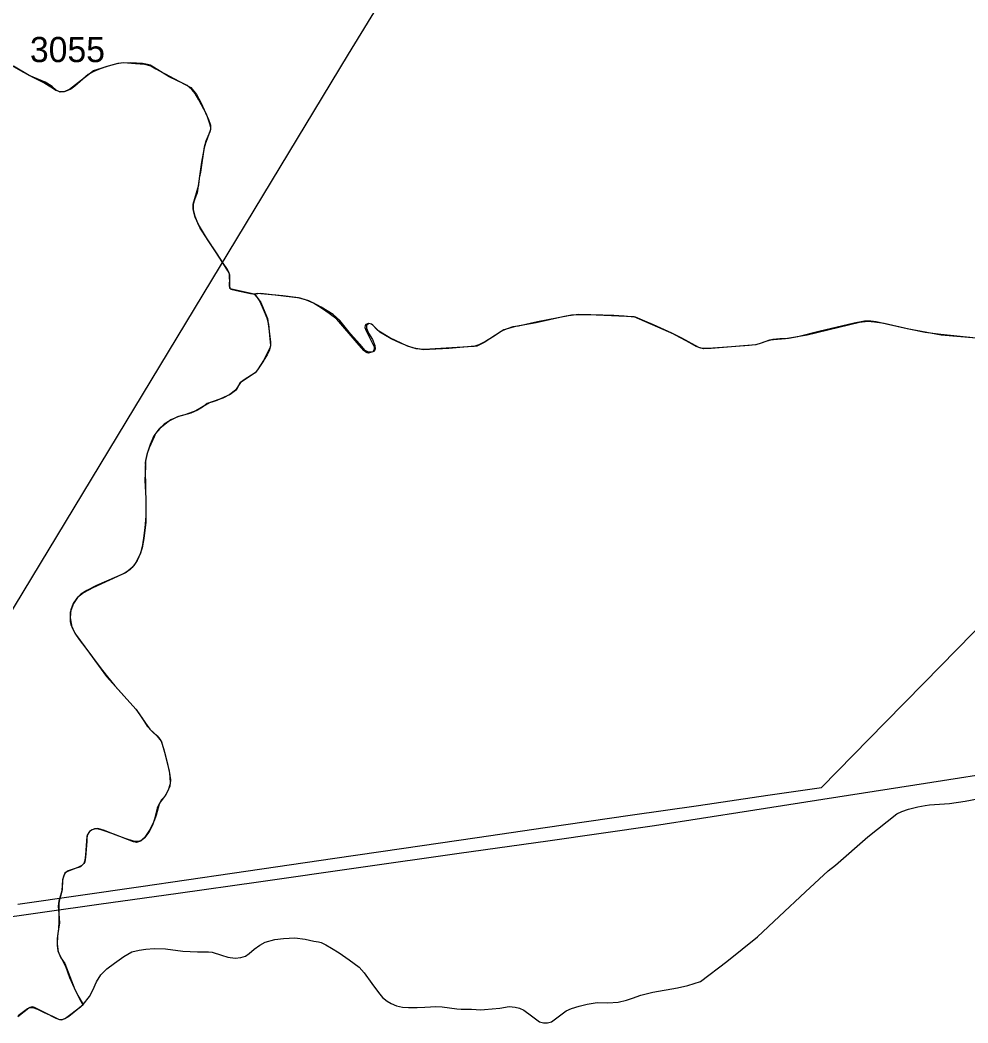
# Model space of a CAD drawing. Extents: x -789162 to -606354, y -1062736 to -945481.
# Drawn here: x -717217 to -713459, y -978569 to -974592 of the extents above; entities that cross this region are included whole.
import ezdxf

# ---------------------------------------------------------------- set-up
doc = ezdxf.new("R2010")
doc.units = 0
for name, color, linetype in [('_SIRSI VZTAHY_CYKLOTRASY MISTNI S', 7, 'Continuous'), ('_SIRSI VZTAHY_CYKLOTRASY MISTNI_POPIS', 7, 'Continuous'), ('_SIRSI VZTAHY_ELEKTRICKE VEDENI VN 220 kV S', 7, 'Continuous'), ('_SIRSI VZTAHY_ELEKTRICKE VEDENI VN 400 kV N', 7, 'Continuous'), ('_SIRSI VZTAHY_ELEKTRICKE VEDENI VN 400 kV S', 7, 'Continuous'), ('_SIRSI VZTAHY_OP vodnich zdroju II stupne', 7, 'Continuous'), ('_SIRSI VZTAHY_SILNICE III TRIDY_STAV', 7, 'Continuous')]:
    doc.layers.add(name, color=color, linetype=linetype)

msp = doc.modelspace()

# ---------------------------------------------------------------- linework, layer by layer
at = {"layer": '_SIRSI VZTAHY_CYKLOTRASY MISTNI S'}
for points in [[(-716288.8, -975678.1), (-716383.8, -975657.6), (-716385.9, -975643.3), (-716386.2, -975598.7), (-716392.7, -975586), (-716413.4, -975554.2), (-716442.2, -975509.8), (-716502.6, -975416.9), (-716522.6, -975373.6), (-716529.6, -975348.1), (-716530.9, -975340.5), (-716530.1, -975321.7), (-716508.3, -975245.2), (-716505.5, -975218.8), (-716500.4, -975194.4), (-716485.5, -975093.9), (-716478.5, -975070.9), (-716462.7, -975033.5), (-716461, -975024), (-716460.1, -975018.8), (-716463, -975006.8), (-716472.8, -974979.7), (-716478.3, -974964.6), (-716508.5, -974907.4), (-716523.3, -974882.7), (-716536.1, -974867), (-716555.1, -974851.5), (-716568, -974844), (-716626.3, -974816.2), (-716660.1, -974795.8), (-716688.3, -974777.9), (-716701.4, -974771.1), (-716712.1, -974767.6), (-716731.9, -974764.5), (-716755.7, -974762.6), (-716780.7, -974761.8), (-716815.5, -974761.9), (-716833, -974764.7), (-716873.1, -974776.3), (-716898.8, -974784.6), (-716924.1, -974795.5), (-716946.7, -974808), (-717000.1, -974854.4), (-717015.9, -974865.8), (-717031.4, -974872.6), (-717042.7, -974876.2), (-717057.8, -974877), (-717065.9, -974873.5), (-717073.3, -974869.4), (-717090.3, -974855.5), (-717111, -974841.5), (-717117.5, -974837.3), (-717180.4, -974810.9), (-717243, -974774.5)], [(-713426.9, -975852.6), (-713565.8, -975839.2), (-713628.1, -975830.1), (-713692.7, -975817.5), (-713790.6, -975795.4), (-713828.9, -975789.7), (-713856.1, -975787.7), (-713888.4, -975790.9), (-714096.1, -975840.9), (-714182.6, -975855.3), (-714245.8, -975861.7), (-714283.1, -975874.9), (-714300.2, -975879.3), (-714476.9, -975894.4), (-714505.4, -975895.6), (-714525.7, -975890), (-714592.7, -975853.2), (-714625.4, -975837.4), (-714782.1, -975769.1), (-714933, -975761.6), (-715002.6, -975760.3), (-715030.5, -975762.5), (-715065.6, -975768.5), (-715170.6, -975792.2), (-715252.5, -975807.3), (-715298.8, -975820.5), (-715309.5, -975826.5), (-715376.5, -975870.5), (-715406.2, -975884.4), (-715428.6, -975886.1), (-715516.8, -975894), (-715619, -975899.3), (-715654.8, -975893.3), (-715675.9, -975886.4), (-715708.7, -975872.8), (-715745.7, -975855.3), (-715790.7, -975828.8), (-715803.3, -975817.9), (-715818.8, -975801), (-715823.4, -975797.1), (-715828.7, -975795.7), (-715835.6, -975795.6), (-715845.8, -975799.3), (-715849, -975803.3), (-715850.2, -975810.3), (-715846.1, -975821.2), (-715812.9, -975887.1), (-715813.2, -975898.1), (-715818.8, -975906.8), (-715835.7, -975912.4), (-715840.5, -975911.6), (-715845.6, -975909.1), (-715853.5, -975901.5), (-715872.4, -975880.6), (-715960.8, -975777.7), (-715991.8, -975755.6), (-716022.4, -975733.8), (-716053, -975715), (-716081.9, -975702.1), (-716106.6, -975694), (-716205.5, -975683), (-716262.8, -975676.7), (-716275.5, -975676.3), (-716288.8, -975678.1), (-716276.9, -975691.7), (-716263, -975711.4), (-716255.9, -975728.2), (-716236.2, -975775.4), (-716228, -975835.9), (-716223.6, -975869.5), (-716223.8, -975881.2), (-716226.1, -975891.7), (-716252.4, -975943.2), (-716275.4, -975978.4), (-716285.4, -975991.2), (-716338.8, -976025.9), (-716345.3, -976031.8), (-716355.6, -976051.4), (-716362.4, -976060.5), (-716383.8, -976076.8), (-716436.7, -976100.6), (-716452.3, -976105.6), (-716475.5, -976112.9), (-716483.7, -976118.9), (-716493.9, -976126.3), (-716513.5, -976138.6), (-716540.5, -976150.3), (-716588.7, -976164.5), (-716602.8, -976170.2), (-716618.7, -976176.7), (-716630.1, -976185.6), (-716663.2, -976211.5), (-716680.3, -976231.7), (-716685.6, -976245.1), (-716705.7, -976288.7), (-716713.4, -976310.1), (-716720.8, -976346.3), (-716720.1, -976362.8), (-716722.2, -976416.6), (-716718.9, -976489.1), (-716718.4, -976584), (-716719.5, -976593.1), (-716725.8, -976647.2), (-716732.9, -976685.1), (-716741, -976708.5), (-716756.2, -976741.3), (-716772.8, -976763.2), (-716795.8, -976782.1), (-716929.1, -976843), (-716966, -976863.7), (-716988.7, -976881.6), (-717002.5, -976901.1), (-717005.6, -976905.5), (-717017.1, -976936.6), (-717018.6, -976940.7), (-717018, -976977.6), (-717015.9, -976989.3), (-717000.4, -977022.7), (-716982.6, -977048.9), (-716952.6, -977088.3), (-716874.6, -977195.1), (-716838.3, -977234.7), (-716758.5, -977324.2), (-716732.3, -977359.8), (-716712.6, -977391.9), (-716692.2, -977414.7), (-716673.9, -977431), (-716657.3, -977451), (-716647, -977484.5), (-716625.9, -977570.8), (-716621, -977605), (-716622.4, -977620.2), (-716629.3, -977645.5), (-716639.7, -977666.2), (-716664.6, -977697.3), (-716673.2, -977717.6), (-716683.6, -977760.8), (-716691.9, -977784.3), (-716706.4, -977811.9), (-716722.6, -977834), (-716739.9, -977848.5), (-716754.7, -977852.7), (-716767.1, -977850.5), (-716845.5, -977820.6), (-716891.5, -977804), (-716912.9, -977799.5), (-716923.8, -977800.3), (-716931.6, -977803.3), (-716941.2, -977809.2), (-716950.9, -977824.7), (-716952, -977839), (-716952.8, -977849.9), (-716957.1, -977911.4), (-716960.6, -977929.4), (-716964, -977937), (-716972.3, -977944.9), (-716987.8, -977952.8), (-717028.6, -977968.7), (-717039.6, -977975.5), (-717044.9, -977988.1), (-717048.3, -978003.3), (-717049.7, -978039.5), (-717053.5, -978056.5), (-717062.1, -978084.4), (-717063.8, -978098.3), (-717063.1, -978167), (-717065.2, -978195.7), (-717070.1, -978234.3), (-717069.7, -978262.3), (-717066.6, -978283), (-717055.5, -978310.3), (-717040, -978332.8), (-716999.9, -978436.4), (-716984.1, -978468.3), (-716968.2, -978497.2), (-716977.8, -978505.9), (-717037, -978551.6), (-717044.2, -978554.5), (-717051.4, -978556.4), (-717059.1, -978556.4), (-717073.9, -978551), (-717117.1, -978529.3), (-717160.2, -978507.6), (-717167, -978505.5), (-717173.2, -978506), (-717177.6, -978507.3), (-717187.8, -978512.8), (-717224.4, -978541.1)]]:
    msp.add_lwpolyline(points, dxfattribs=at)
at = {"layer": '_SIRSI VZTAHY_ELEKTRICKE VEDENI VN 220 kV S'}
msp.add_lwpolyline([(-717343.6, -978160.4), (-716904.9, -978098.1), (-716590.7, -978053.8), (-716271.9, -978008.8), (-715874.9, -977952.5), (-715475.9, -977896), (-715124.1, -977846.1), (-714701.5, -977786.3), (-714329.4, -977728.1), (-714033.6, -977682), (-713669.8, -977625.1), (-713248, -977559.1)], dxfattribs=at)
at = {"layer": '_SIRSI VZTAHY_ELEKTRICKE VEDENI VN 400 kV N'}
msp.add_lwpolyline([(-717225.4, -978097.6), (-716737.9, -978028.2), (-716376.5, -977975.2), (-715969.3, -977915.3), (-715704.7, -977877), (-715405.2, -977833.5), (-715134.8, -977794.2), (-714798.2, -977745.3), (-714526.9, -977706), (-714252.9, -977666.2), (-714040, -977635.2), (-713786.8, -977377.3), (-713633.3, -977221.5), (-713373.6, -976955.3)], dxfattribs=at)
at = {"layer": '_SIRSI VZTAHY_ELEKTRICKE VEDENI VN 400 kV S'}
msp.add_lwpolyline([(-717225.4, -978097.6), (-716737.9, -978028.2), (-716376.5, -977975.2), (-715969.3, -977915.3), (-715704.7, -977877), (-715405.2, -977833.5), (-715134.8, -977794.2), (-714798.2, -977745.3), (-714526.9, -977706), (-714252.9, -977666.2), (-714040, -977635.2), (-713786.8, -977377.3), (-713633.3, -977221.5), (-713373.6, -976955.3)], dxfattribs=at)
at = {"layer": '_SIRSI VZTAHY_OP vodnich zdroju II stupne'}
msp.add_lwpolyline([(-715266.5, -973663.8), (-715915.9, -974727.4), (-717274.7, -976974.1)], dxfattribs=at)
at = {"layer": '_SIRSI VZTAHY_SILNICE III TRIDY_STAV'}
for points in [[(-717249, -974771.3), (-717206.1, -974797), (-717163.6, -974819.2), (-717119.4, -974842.1), (-717094.8, -974856.1), (-717075.3, -974869.7), (-717060.7, -974874.5), (-717041, -974874.8), (-717021, -974865.3), (-716925.4, -974792.3), (-716891.8, -974781.2), (-716856.9, -974770.2), (-716828.6, -974761.9), (-716806.6, -974759.8), (-716759, -974763.3), (-716723.5, -974765.9), (-716698.7, -974773.5), (-716678.8, -974784.5), (-716607.9, -974823.7), (-716539.4, -974859.1), (-716517.1, -974887.3), (-716498.5, -974921.8), (-716470.1, -974986.3), (-716461.8, -975008.9), (-716462.2, -975026.2), (-716475.8, -975062.4), (-716482.2, -975079.3), (-716487.5, -975098.9), (-716497.1, -975155.4), (-716514.4, -975277.2), (-716524.7, -975300.8), (-716530.9, -975322.2), (-716531.1, -975344.7), (-716524.7, -975369.8), (-716511.1, -975402.8), (-716475.2, -975461.6), (-716439.9, -975515.2), (-716412.4, -975555.8), (-716395.5, -975580.4), (-716390.7, -975590.1), (-716386.9, -975602), (-716386, -975615.2), (-716388.2, -975645.4), (-716386, -975653), (-716381.3, -975658.5), (-716359.4, -975664.5), (-716303.8, -975675.7), (-716286.3, -975678.2)], [(-716286.3, -975678.2), (-716265.7, -975707.6), (-716253, -975737.8), (-716239, -975772.1), (-716232.3, -975797.5), (-716227.6, -975841.6), (-716223.5, -975882.5), (-716227.9, -975899.4), (-716237.1, -975918.8), (-716275.2, -975978.8), (-716285, -975991.1), (-716327.9, -976017.8), (-716342.9, -976028.9), (-716362.2, -976059.4), (-716385.7, -976077.2), (-716413, -976090.6), (-716462.7, -976108.6), (-716475.8, -976114.3), (-716520.3, -976141.3), (-716563.3, -976156.8), (-716592.2, -976165.8), (-716622.2, -976179.1), (-716646, -976194.7), (-716666.7, -976214.7), (-716686, -976241), (-716701.3, -976274.4), (-716714.3, -976315), (-716719.7, -976338.2), (-716721.1, -976376.6), (-716718.3, -976509.7), (-716718.7, -976557.6), (-716722.2, -976605.5), (-716727.3, -976646.8), (-716732.7, -976680.8), (-716739, -976706.1), (-716752.8, -976735), (-716765.9, -976754.3), (-716782.4, -976771.5), (-716803.8, -976786), (-716914, -976834.7), (-716951.7, -976854.4), (-716975.9, -976868.7), (-716991.5, -976884), (-717006.4, -976905.2), (-717015.7, -976930.2), (-717018.5, -976962.9), (-717011.2, -976999.7), (-716997.6, -977027.3), (-716959.6, -977077.9), (-716898.8, -977159.9), (-716870.5, -977195.7), (-716840.6, -977232.2), (-716756.6, -977326.4), (-716719.8, -977380.2), (-716701.9, -977403.9), (-716673.2, -977430.9), (-716662.2, -977443.1), (-716655.9, -977454.5), (-716644.1, -977494.5), (-716633, -977541.5), (-716625.1, -977578), (-716622.8, -977596.7), (-716621.5, -977614.2), (-716623.8, -977629.4), (-716633, -977650.7), (-716644.6, -977671.6), (-716656.8, -977684.7), (-716665.7, -977700.8), (-716677.9, -977745.4), (-716685.1, -977767.2), (-716703.2, -977804.6), (-716725.4, -977835.8), (-716736.8, -977846.6), (-716749.5, -977849.5), (-716766.7, -977847.6), (-716796.8, -977839), (-716840, -977822.5), (-716882.1, -977805.7), (-716908.3, -977798.2), (-716921.8, -977798.8), (-716936.9, -977805.7), (-716947, -977817.7), (-716952.7, -977828.8), (-716957.8, -977902.8), (-716960.3, -977925), (-716963.8, -977936.5), (-716977.9, -977950.3), (-717002.3, -977957.1), (-717026.7, -977966.3), (-717038.5, -977973.9), (-717043.5, -977985.3), (-717049.2, -978001.2), (-717051.2, -978044.5), (-717063.6, -978085.8), (-717065.4, -978105.4), (-717063.9, -978134.6), (-717060.4, -978172.1), (-717064.6, -978196.4), (-717069.1, -978223.1), (-717070.2, -978256.8), (-717066.1, -978286.4), (-717051.8, -978316.4), (-717036.8, -978343.7), (-717020.7, -978389.2), (-717003, -978429.7), (-716988.5, -978460.4), (-716966.4, -978495.7)], [(-713440.6, -975852.1), (-713564.8, -975841.1), (-713699.9, -975815.6), (-713822.6, -975788.6), (-713844.5, -975786.4), (-713869.4, -975786), (-713909.7, -975793.3), (-714049.8, -975826.3), (-714133.6, -975848.1), (-714170.8, -975854.8), (-714204.8, -975856.3), (-714233, -975858.9), (-714256.7, -975865.6), (-714282.4, -975874), (-714300.9, -975879), (-714326, -975882.5), (-714431.8, -975889.7), (-714490.8, -975894.4), (-714517.9, -975892.2), (-714536.5, -975886.2), (-714562.2, -975871.2), (-714633.5, -975832.8), (-714705.1, -975800.9), (-714739.4, -975785.9), (-714777.6, -975770), (-714794.2, -975768), (-714822.2, -975766.1), (-714862.3, -975763.6), (-714906.2, -975762.4), (-715001.4, -975759.8), (-715043, -975764.7), (-715165.2, -975788.8), (-715241.2, -975805.6), (-715263.2, -975808.7), (-715285.1, -975816), (-715305.9, -975824.1), (-715332.9, -975842.8), (-715371.5, -975866.7), (-715398.4, -975880.1), (-715418, -975885.7), (-715614.5, -975898.6), (-715647.2, -975895.8), (-715681.2, -975885.5), (-715751.5, -975851.5), (-715794.6, -975825.2), (-715809.4, -975810.6), (-715822.7, -975797.6), (-715833.9, -975794.9), (-715842.8, -975802.8), (-715842.8, -975814), (-715835, -975833.1), (-715819.9, -975857.9), (-715810.7, -975881.7), (-715809, -975895.9), (-715812.4, -975905.8), (-715823.8, -975908.8), (-715835.7, -975908.4), (-715849.2, -975902.6), (-715870.3, -975876.8), (-715907.3, -975836.4), (-715948.8, -975783.7), (-715976.2, -975759.6), (-716022.6, -975729.8), (-716040.1, -975720.9), (-716072.6, -975704.7), (-716113, -975692.9), (-716174.6, -975685.6), (-716217.2, -975681.2), (-716262.1, -975676.1), (-716286.3, -975678.2)], [(-716966.4, -978495.7), (-716942.3, -978464.3), (-716928.4, -978439.3), (-716914.5, -978406), (-716896.6, -978377.7), (-716872.5, -978354.5), (-716843, -978332.3), (-716805.8, -978305), (-716774.4, -978287.5), (-716745.2, -978280.2), (-716718.5, -978275.8), (-716685.4, -978274.1), (-716640.6, -978275.4), (-716572.1, -978284), (-716514, -978286.9), (-716469.7, -978287.4), (-716455.4, -978288.7), (-716418.4, -978299.8), (-716393.1, -978308.2), (-716364.2, -978312.6), (-716341.3, -978309.7), (-716323.5, -978304.3), (-716308, -978293.9), (-716288.3, -978277), (-716265.7, -978259.9), (-716245.6, -978249.1), (-716207, -978238.6), (-716172.5, -978234), (-716127.3, -978231), (-716086.4, -978236.1), (-716052.9, -978244.1), (-716033.3, -978247.5), (-716023.2, -978250.1), (-716004.5, -978259.2), (-715982.2, -978272), (-715952.4, -978291), (-715911.7, -978319), (-715873, -978348.2), (-715852.1, -978369.7), (-715822.1, -978411.9), (-715795.8, -978448.8), (-715780, -978467.9), (-715761.6, -978482.1), (-715746.3, -978492.3), (-715724.5, -978501.4), (-715701.2, -978506), (-715676.5, -978507.9), (-715642.2, -978507.6), (-715612.1, -978505.8), (-715589.1, -978504.9), (-715570.4, -978504.3), (-715544.1, -978504.4), (-715485.3, -978512.9), (-715467.5, -978514.6), (-715426.6, -978514.2), (-715389.7, -978517.1), (-715375.5, -978516.1), (-715314.9, -978509.9), (-715277.7, -978503.7), (-715253.4, -978505.8), (-715237.1, -978509.7), (-715219.9, -978518.3), (-715189.7, -978540.6), (-715157.2, -978564.1), (-715142.1, -978568.9), (-715125.9, -978568.7), (-715110.2, -978564.4), (-715051.3, -978521.5), (-715030.2, -978511.5), (-714999.8, -978502.1), (-714968.7, -978494.9), (-714929.1, -978488.5), (-714886.2, -978489.1), (-714846.2, -978486.3), (-714813.2, -978478.7), (-714788.7, -978471.3), (-714756, -978458.7), (-714707.9, -978447.1), (-714611, -978429.4), (-714569.7, -978419.9), (-714519.8, -978405), (-714414.4, -978325), (-714293.1, -978227.8), (-714207, -978146.5), (-714102.9, -978048.6), (-714012.6, -977965.9), (-713983.5, -977943.3), (-713855.3, -977830.6), (-713779, -977769.5), (-713740.7, -977740.1), (-713721.3, -977730.6), (-713694, -977720.8), (-713658.2, -977711.9), (-713628.2, -977706.1), (-713611.7, -977704.1), (-713532.7, -977698.9), (-713470.2, -977688.8), (-713421.6, -977680.8)], [(-717225.9, -978543.4), (-717182.4, -978508.5), (-717166.2, -978507.2), (-717147.8, -978513.9), (-717123.7, -978526.8), (-717085.3, -978543.7), (-717064.3, -978554.5), (-717050.9, -978556.4), (-717039.7, -978550.8), (-717023.7, -978542.1), (-716966.4, -978495.7)]]:
    msp.add_lwpolyline(points, dxfattribs=at)

# ---------------------------------------------------------------- texts
at = {"layer": '_SIRSI VZTAHY_CYKLOTRASY MISTNI_POPIS'}
msp.add_text('3055', height=100, dxfattribs=at).set_placement((-717177.8, -974758.5))

doc.saveas('drawing.dxf')
